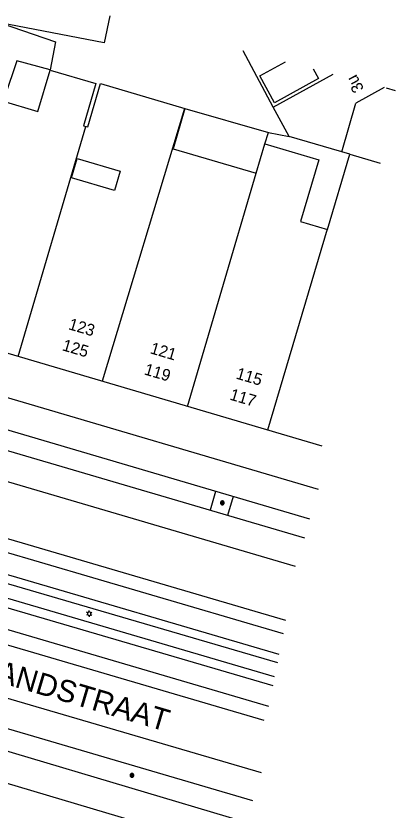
# Model space of a CAD drawing. Extents: x 81065 to 81486, y 452384 to 452681.
# Drawn here: x 81331.8 to 81357.7, y 452503.7 to 452557.9 of the extents above; entities that cross this region are included whole.
import ezdxf

# ---------------------------------------------------------------- set-up
doc = ezdxf.new("R2010")
doc.units = 0
for name, color, linetype in [('B-BH-AL-TOPOGRAFIE_HUISNUMMER-T25', 7, 'Continuous'), ('B-BH-AL-TOPOGRAFIE_STRAATNAAM-S', 7, 'Continuous'), ('B-BH-GR-BOOM-S', 7, 'Continuous'), ('B-BH-IE-MEUBILAIR_WEGMEUBILAIR_LICHTMAST-S', 7, 'Continuous'), ('B-BH-OG-TERREIN_ERF-GV', 7, 'Continuous'), ('B-BH-OG-TOPOGRAFIE_BEBOUWING-GV', 7, 'Continuous'), ('B-BH-OG-TOPOGRAFIE_BEBOUWING_PANDSCHEIDING-GV', 7, 'Continuous'), ('B-BH-VH-KANTOPSLUITING-GV', 7, 'Continuous'), ('B-SB-OG-WEG_SPOOR_TRAM-G', 7, 'Continuous')]:
    doc.layers.add(name, color=color, linetype=linetype)

msp = doc.modelspace()

# ---------------------------------------------------------------- linework, layer by layer
at = {"layer": 'B-BH-GR-BOOM-S'}
for points in [[(81345.8, 452524.656), (81345.8, 452524.643), (81345.802, 452524.63), (81345.806, 452524.616), (81345.811, 452524.604), (81345.817, 452524.592), (81345.824, 452524.581), (81345.833, 452524.57), (81345.842, 452524.561), (81345.853, 452524.552), (81345.864, 452524.545), (81345.876, 452524.539), (81345.889, 452524.534), (81345.902, 452524.53), (81345.915, 452524.528), (81345.928, 452524.527), (81345.942, 452524.528), (81345.955, 452524.53), (81345.968, 452524.534), (81345.981, 452524.539), (81345.993, 452524.545), (81346.004, 452524.552), (81346.015, 452524.561), (81346.024, 452524.57), (81346.033, 452524.581), (81346.04, 452524.592), (81346.046, 452524.604), (81346.051, 452524.616), (81346.054, 452524.63), (81346.056, 452524.643), (81346.057, 452524.656), (81346.056, 452524.67), (81346.054, 452524.683), (81346.051, 452524.696), (81346.046, 452524.709), (81346.04, 452524.721), (81346.033, 452524.732), (81346.024, 452524.743), (81346.015, 452524.752), (81346.004, 452524.761), (81345.993, 452524.768), (81345.981, 452524.774), (81345.968, 452524.779), (81345.955, 452524.782), (81345.942, 452524.784), (81345.928, 452524.785), (81345.915, 452524.784), (81345.902, 452524.782), (81345.889, 452524.779), (81345.876, 452524.774), (81345.864, 452524.768), (81345.853, 452524.761), (81345.842, 452524.752), (81345.833, 452524.743), (81345.824, 452524.732), (81345.817, 452524.721), (81345.811, 452524.709), (81345.806, 452524.696), (81345.802, 452524.683), (81345.8, 452524.67), (81345.8, 452524.656)], [(81345.824, 452524.656), (81345.825, 452524.645), (81345.826, 452524.635), (81345.829, 452524.624), (81345.833, 452524.614), (81345.838, 452524.604), (81345.844, 452524.595), (81345.851, 452524.586), (81345.858, 452524.579), (81345.867, 452524.572), (81345.876, 452524.566), (81345.886, 452524.561), (81345.896, 452524.557), (81345.907, 452524.554), (81345.917, 452524.552), (81345.928, 452524.552), (81345.939, 452524.552), (81345.95, 452524.554), (81345.961, 452524.557), (81345.971, 452524.561), (81345.981, 452524.566), (81345.99, 452524.572), (81345.998, 452524.579), (81346.006, 452524.586), (81346.013, 452524.595), (81346.019, 452524.604), (81346.024, 452524.614), (81346.028, 452524.624), (81346.03, 452524.635), (81346.032, 452524.645), (81346.033, 452524.656), (81346.032, 452524.667), (81346.03, 452524.678), (81346.028, 452524.689), (81346.024, 452524.699), (81346.019, 452524.709), (81346.013, 452524.718), (81346.006, 452524.726), (81345.998, 452524.734), (81345.99, 452524.741), (81345.981, 452524.747), (81345.971, 452524.752), (81345.961, 452524.756), (81345.95, 452524.758), (81345.939, 452524.76), (81345.928, 452524.761), (81345.917, 452524.76), (81345.907, 452524.758), (81345.896, 452524.756), (81345.886, 452524.752), (81345.876, 452524.747), (81345.867, 452524.741), (81345.858, 452524.734), (81345.851, 452524.726), (81345.844, 452524.718), (81345.838, 452524.709), (81345.833, 452524.699), (81345.829, 452524.689), (81345.826, 452524.678), (81345.825, 452524.667), (81345.824, 452524.656)], [(81345.847, 452524.656), (81345.847, 452524.648), (81345.849, 452524.639), (81345.851, 452524.631), (81345.854, 452524.623), (81345.858, 452524.615), (81345.862, 452524.608), (81345.868, 452524.602), (81345.874, 452524.596), (81345.88, 452524.59), (81345.888, 452524.586), (81345.895, 452524.582), (81345.903, 452524.579), (81345.911, 452524.577), (81345.92, 452524.575), (81345.928, 452524.575), (81345.937, 452524.575), (81345.945, 452524.577), (81345.954, 452524.579), (81345.962, 452524.582), (81345.969, 452524.586), (81345.976, 452524.59), (81345.983, 452524.596), (81345.989, 452524.602), (81345.994, 452524.608), (81345.999, 452524.615), (81346.003, 452524.623), (81346.006, 452524.631), (81346.008, 452524.639), (81346.009, 452524.648), (81346.01, 452524.656), (81346.009, 452524.665), (81346.008, 452524.673), (81346.006, 452524.682), (81346.003, 452524.689), (81345.999, 452524.697), (81345.994, 452524.704), (81345.989, 452524.711), (81345.983, 452524.717), (81345.976, 452524.722), (81345.969, 452524.727), (81345.962, 452524.731), (81345.954, 452524.734), (81345.945, 452524.736), (81345.937, 452524.737), (81345.928, 452524.738), (81345.92, 452524.737), (81345.911, 452524.736), (81345.903, 452524.734), (81345.895, 452524.731), (81345.888, 452524.727), (81345.88, 452524.722), (81345.874, 452524.717), (81345.868, 452524.711), (81345.862, 452524.704), (81345.858, 452524.697), (81345.854, 452524.689), (81345.851, 452524.682), (81345.849, 452524.673), (81345.847, 452524.665), (81345.847, 452524.656)], [(81345.87, 452524.656), (81345.87, 452524.65), (81345.871, 452524.644), (81345.873, 452524.638), (81345.875, 452524.632), (81345.878, 452524.627), (81345.881, 452524.622), (81345.885, 452524.617), (81345.889, 452524.613), (81345.894, 452524.609), (81345.899, 452524.605), (81345.905, 452524.603), (81345.91, 452524.6), (81345.916, 452524.599), (81345.922, 452524.598), (81345.928, 452524.598), (81345.935, 452524.598), (81345.941, 452524.599), (81345.947, 452524.6), (81345.952, 452524.603), (81345.958, 452524.605), (81345.963, 452524.609), (81345.968, 452524.613), (81345.972, 452524.617), (81345.976, 452524.622), (81345.979, 452524.627), (81345.982, 452524.632), (81345.984, 452524.638), (81345.986, 452524.644), (81345.987, 452524.65), (81345.987, 452524.656), (81345.987, 452524.662), (81345.986, 452524.668), (81345.984, 452524.674), (81345.982, 452524.68), (81345.979, 452524.686), (81345.976, 452524.691), (81345.972, 452524.696), (81345.968, 452524.7), (81345.963, 452524.704), (81345.958, 452524.707), (81345.952, 452524.71), (81345.947, 452524.712), (81345.941, 452524.714), (81345.935, 452524.715), (81345.928, 452524.715), (81345.922, 452524.715), (81345.916, 452524.714), (81345.91, 452524.712), (81345.905, 452524.71), (81345.899, 452524.707), (81345.894, 452524.704), (81345.889, 452524.7), (81345.885, 452524.696), (81345.881, 452524.691), (81345.878, 452524.686), (81345.875, 452524.68), (81345.873, 452524.674), (81345.871, 452524.668), (81345.87, 452524.662), (81345.87, 452524.656)], [(81345.893, 452524.656), (81345.893, 452524.653), (81345.893, 452524.649), (81345.894, 452524.645), (81345.896, 452524.642), (81345.897, 452524.638), (81345.899, 452524.635), (81345.902, 452524.632), (81345.904, 452524.63), (81345.907, 452524.627), (81345.91, 452524.625), (81345.914, 452524.624), (81345.917, 452524.622), (81345.921, 452524.621), (81345.925, 452524.621), (81345.928, 452524.62), (81345.932, 452524.621), (81345.936, 452524.621), (81345.939, 452524.622), (81345.943, 452524.624), (81345.946, 452524.625), (81345.949, 452524.627), (81345.952, 452524.63), (81345.955, 452524.632), (81345.957, 452524.635), (81345.959, 452524.638), (81345.961, 452524.642), (81345.962, 452524.645), (81345.963, 452524.649), (81345.964, 452524.653), (81345.964, 452524.656), (81345.964, 452524.66), (81345.963, 452524.664), (81345.962, 452524.667), (81345.961, 452524.671), (81345.959, 452524.674), (81345.957, 452524.677), (81345.955, 452524.68), (81345.952, 452524.683), (81345.949, 452524.685), (81345.946, 452524.687), (81345.943, 452524.689), (81345.939, 452524.69), (81345.936, 452524.691), (81345.932, 452524.692), (81345.928, 452524.692), (81345.925, 452524.692), (81345.921, 452524.691), (81345.917, 452524.69), (81345.914, 452524.689), (81345.91, 452524.687), (81345.907, 452524.685), (81345.904, 452524.683), (81345.902, 452524.68), (81345.899, 452524.677), (81345.897, 452524.674), (81345.896, 452524.671), (81345.894, 452524.667), (81345.893, 452524.664), (81345.893, 452524.66), (81345.893, 452524.656)], [(81345.915, 452524.656), (81345.915, 452524.655), (81345.916, 452524.654), (81345.916, 452524.652), (81345.917, 452524.651), (81345.917, 452524.65), (81345.918, 452524.649), (81345.919, 452524.648), (81345.92, 452524.647), (81345.921, 452524.646), (81345.922, 452524.645), (81345.923, 452524.645), (81345.924, 452524.644), (81345.926, 452524.644), (81345.927, 452524.643), (81345.928, 452524.643), (81345.93, 452524.643), (81345.931, 452524.644), (81345.932, 452524.644), (81345.934, 452524.645), (81345.935, 452524.645), (81345.936, 452524.646), (81345.937, 452524.647), (81345.938, 452524.648), (81345.939, 452524.649), (81345.94, 452524.65), (81345.94, 452524.651), (81345.941, 452524.652), (81345.941, 452524.654), (81345.941, 452524.655), (81345.941, 452524.656), (81345.941, 452524.658), (81345.941, 452524.659), (81345.941, 452524.66), (81345.94, 452524.662), (81345.94, 452524.663), (81345.939, 452524.664), (81345.938, 452524.665), (81345.937, 452524.666), (81345.936, 452524.667), (81345.935, 452524.667), (81345.934, 452524.668), (81345.932, 452524.669), (81345.931, 452524.669), (81345.93, 452524.669), (81345.928, 452524.669), (81345.927, 452524.669), (81345.926, 452524.669), (81345.924, 452524.669), (81345.923, 452524.668), (81345.922, 452524.667), (81345.921, 452524.667), (81345.92, 452524.666), (81345.919, 452524.665), (81345.918, 452524.664), (81345.917, 452524.663), (81345.917, 452524.662), (81345.916, 452524.66), (81345.916, 452524.659), (81345.915, 452524.658), (81345.915, 452524.656)], [(81339.627, 452506.026), (81339.628, 452506.012), (81339.63, 452505.999), (81339.633, 452505.986), (81339.638, 452505.974), (81339.644, 452505.962), (81339.652, 452505.95), (81339.66, 452505.94), (81339.67, 452505.93), (81339.68, 452505.922), (81339.692, 452505.914), (81339.704, 452505.908), (81339.716, 452505.903), (81339.729, 452505.9), (81339.742, 452505.898), (81339.756, 452505.897), (81339.769, 452505.898), (81339.783, 452505.9), (81339.796, 452505.903), (81339.808, 452505.908), (81339.82, 452505.914), (81339.832, 452505.922), (81339.842, 452505.93), (81339.852, 452505.94), (81339.86, 452505.95), (81339.868, 452505.962), (81339.874, 452505.974), (81339.878, 452505.986), (81339.882, 452505.999), (81339.884, 452506.012), (81339.885, 452506.026), (81339.884, 452506.039), (81339.882, 452506.053), (81339.878, 452506.066), (81339.874, 452506.078), (81339.868, 452506.09), (81339.86, 452506.102), (81339.852, 452506.112), (81339.842, 452506.122), (81339.832, 452506.13), (81339.82, 452506.138), (81339.808, 452506.144), (81339.796, 452506.148), (81339.783, 452506.152), (81339.769, 452506.154), (81339.756, 452506.155), (81339.742, 452506.154), (81339.729, 452506.152), (81339.716, 452506.148), (81339.704, 452506.144), (81339.692, 452506.138), (81339.68, 452506.13), (81339.67, 452506.122), (81339.66, 452506.112), (81339.652, 452506.102), (81339.644, 452506.09), (81339.638, 452506.078), (81339.633, 452506.066), (81339.63, 452506.053), (81339.628, 452506.039), (81339.627, 452506.026)], [(81339.652, 452506.026), (81339.652, 452506.015), (81339.654, 452506.004), (81339.657, 452505.994), (81339.661, 452505.983), (81339.665, 452505.974), (81339.671, 452505.965), (81339.678, 452505.956), (81339.686, 452505.948), (81339.695, 452505.941), (81339.704, 452505.935), (81339.713, 452505.931), (81339.724, 452505.927), (81339.734, 452505.924), (81339.745, 452505.922), (81339.756, 452505.922), (81339.767, 452505.922), (81339.778, 452505.924), (81339.788, 452505.927), (81339.798, 452505.931), (81339.808, 452505.935), (81339.817, 452505.941), (81339.826, 452505.948), (81339.834, 452505.956), (81339.84, 452505.965), (81339.846, 452505.974), (81339.851, 452505.983), (81339.855, 452505.994), (81339.858, 452506.004), (81339.86, 452506.015), (81339.86, 452506.026), (81339.86, 452506.037), (81339.858, 452506.048), (81339.855, 452506.058), (81339.851, 452506.068), (81339.846, 452506.078), (81339.84, 452506.087), (81339.834, 452506.096), (81339.826, 452506.104), (81339.817, 452506.11), (81339.808, 452506.116), (81339.798, 452506.121), (81339.788, 452506.125), (81339.778, 452506.128), (81339.767, 452506.13), (81339.756, 452506.13), (81339.745, 452506.13), (81339.734, 452506.128), (81339.724, 452506.125), (81339.713, 452506.121), (81339.704, 452506.116), (81339.695, 452506.11), (81339.686, 452506.104), (81339.678, 452506.096), (81339.671, 452506.087), (81339.665, 452506.078), (81339.661, 452506.068), (81339.657, 452506.058), (81339.654, 452506.048), (81339.652, 452506.037), (81339.652, 452506.026)], [(81339.674, 452506.026), (81339.675, 452506.017), (81339.676, 452506.009), (81339.678, 452506.001), (81339.681, 452505.993), (81339.685, 452505.985), (81339.69, 452505.978), (81339.695, 452505.971), (81339.701, 452505.965), (81339.708, 452505.96), (81339.715, 452505.955), (81339.723, 452505.951), (81339.731, 452505.948), (81339.739, 452505.946), (81339.747, 452505.945), (81339.756, 452505.944), (81339.764, 452505.945), (81339.773, 452505.946), (81339.781, 452505.948), (81339.789, 452505.951), (81339.797, 452505.955), (81339.804, 452505.96), (81339.811, 452505.965), (81339.817, 452505.971), (81339.822, 452505.978), (81339.827, 452505.985), (81339.83, 452505.993), (81339.834, 452506.001), (81339.836, 452506.009), (81339.837, 452506.017), (81339.838, 452506.026), (81339.837, 452506.034), (81339.836, 452506.043), (81339.834, 452506.051), (81339.83, 452506.059), (81339.827, 452506.067), (81339.822, 452506.074), (81339.817, 452506.081), (81339.811, 452506.087), (81339.804, 452506.092), (81339.797, 452506.097), (81339.789, 452506.1), (81339.781, 452506.104), (81339.773, 452506.106), (81339.764, 452506.107), (81339.756, 452506.108), (81339.747, 452506.107), (81339.739, 452506.106), (81339.731, 452506.104), (81339.723, 452506.1), (81339.715, 452506.097), (81339.708, 452506.092), (81339.701, 452506.087), (81339.695, 452506.081), (81339.69, 452506.074), (81339.685, 452506.067), (81339.681, 452506.059), (81339.678, 452506.051), (81339.676, 452506.043), (81339.675, 452506.034), (81339.674, 452506.026)], [(81339.697, 452506.026), (81339.698, 452506.02), (81339.699, 452506.014), (81339.7, 452506.008), (81339.702, 452506.002), (81339.705, 452505.997), (81339.709, 452505.991), (81339.712, 452505.987), (81339.717, 452505.982), (81339.721, 452505.979), (81339.727, 452505.975), (81339.732, 452505.972), (81339.738, 452505.97), (81339.744, 452505.969), (81339.75, 452505.968), (81339.756, 452505.967), (81339.762, 452505.968), (81339.768, 452505.969), (81339.774, 452505.97), (81339.78, 452505.972), (81339.785, 452505.975), (81339.79, 452505.979), (81339.795, 452505.982), (81339.8, 452505.987), (81339.803, 452505.991), (81339.807, 452505.997), (81339.81, 452506.002), (81339.812, 452506.008), (81339.813, 452506.014), (81339.814, 452506.02), (81339.815, 452506.026), (81339.814, 452506.032), (81339.813, 452506.038), (81339.812, 452506.044), (81339.81, 452506.05), (81339.807, 452506.055), (81339.803, 452506.06), (81339.8, 452506.065), (81339.795, 452506.07), (81339.79, 452506.073), (81339.785, 452506.077), (81339.78, 452506.08), (81339.774, 452506.082), (81339.768, 452506.083), (81339.762, 452506.084), (81339.756, 452506.085), (81339.75, 452506.084), (81339.744, 452506.083), (81339.738, 452506.082), (81339.732, 452506.08), (81339.727, 452506.077), (81339.721, 452506.073), (81339.717, 452506.07), (81339.712, 452506.065), (81339.709, 452506.06), (81339.705, 452506.055), (81339.702, 452506.05), (81339.7, 452506.044), (81339.699, 452506.038), (81339.698, 452506.032), (81339.697, 452506.026)], [(81339.72, 452506.026), (81339.72, 452506.022), (81339.721, 452506.019), (81339.722, 452506.015), (81339.723, 452506.011), (81339.725, 452506.008), (81339.727, 452506.005), (81339.729, 452506.002), (81339.732, 452505.999), (81339.735, 452505.997), (81339.738, 452505.995), (81339.741, 452505.993), (81339.745, 452505.992), (81339.749, 452505.991), (81339.752, 452505.99), (81339.756, 452505.99), (81339.76, 452505.99), (81339.763, 452505.991), (81339.767, 452505.992), (81339.771, 452505.993), (81339.774, 452505.995), (81339.777, 452505.997), (81339.78, 452505.999), (81339.782, 452506.002), (81339.785, 452506.005), (81339.787, 452506.008), (81339.789, 452506.011), (81339.79, 452506.015), (81339.791, 452506.019), (81339.792, 452506.022), (81339.792, 452506.026), (81339.792, 452506.03), (81339.791, 452506.033), (81339.79, 452506.037), (81339.789, 452506.041), (81339.787, 452506.044), (81339.785, 452506.047), (81339.782, 452506.05), (81339.78, 452506.052), (81339.777, 452506.055), (81339.774, 452506.057), (81339.771, 452506.059), (81339.767, 452506.06), (81339.763, 452506.061), (81339.76, 452506.062), (81339.756, 452506.062), (81339.752, 452506.062), (81339.749, 452506.061), (81339.745, 452506.06), (81339.741, 452506.059), (81339.738, 452506.057), (81339.735, 452506.055), (81339.732, 452506.052), (81339.729, 452506.05), (81339.727, 452506.047), (81339.725, 452506.044), (81339.723, 452506.041), (81339.722, 452506.037), (81339.721, 452506.033), (81339.72, 452506.03), (81339.72, 452506.026)], [(81339.743, 452506.026), (81339.743, 452506.025), (81339.743, 452506.023), (81339.744, 452506.022), (81339.744, 452506.021), (81339.745, 452506.02), (81339.746, 452506.018), (81339.746, 452506.017), (81339.747, 452506.016), (81339.748, 452506.016), (81339.75, 452506.015), (81339.751, 452506.014), (81339.752, 452506.014), (81339.753, 452506.013), (81339.755, 452506.013), (81339.756, 452506.013), (81339.757, 452506.013), (81339.759, 452506.013), (81339.76, 452506.014), (81339.761, 452506.014), (81339.762, 452506.015), (81339.764, 452506.016), (81339.765, 452506.016), (81339.766, 452506.017), (81339.766, 452506.018), (81339.767, 452506.02), (81339.768, 452506.021), (81339.768, 452506.022), (81339.769, 452506.023), (81339.769, 452506.025), (81339.769, 452506.026), (81339.769, 452506.027), (81339.769, 452506.029), (81339.768, 452506.03), (81339.768, 452506.031), (81339.767, 452506.032), (81339.766, 452506.034), (81339.766, 452506.035), (81339.765, 452506.036), (81339.764, 452506.036), (81339.762, 452506.037), (81339.761, 452506.038), (81339.76, 452506.038), (81339.759, 452506.039), (81339.757, 452506.039), (81339.756, 452506.039), (81339.755, 452506.039), (81339.753, 452506.039), (81339.752, 452506.038), (81339.751, 452506.038), (81339.75, 452506.037), (81339.748, 452506.036), (81339.747, 452506.036), (81339.746, 452506.035), (81339.746, 452506.034), (81339.745, 452506.032), (81339.744, 452506.031), (81339.744, 452506.03), (81339.743, 452506.029), (81339.743, 452506.027), (81339.743, 452506.026)]]:
    msp.add_lwpolyline(points, dxfattribs=at)
at = {"layer": 'B-BH-IE-MEUBILAIR_WEGMEUBILAIR_LICHTMAST-S'}
for p, q in [((81336.835, 452517.199), (81336.835, 452517.291)), ((81336.729, 452517.138), (81336.65, 452517.184)), ((81336.729, 452517.016), (81336.65, 452516.97)), ((81336.835, 452516.955), (81336.835, 452516.863)), ((81336.94, 452517.138), (81337.02, 452517.184)), ((81336.94, 452517.016), (81337.02, 452516.97))]:
    msp.add_line(p, q, dxfattribs=at)
msp.add_lwpolyline([(81336.713, 452517.077), (81336.714, 452517.064), (81336.715, 452517.051), (81336.719, 452517.039), (81336.723, 452517.027), (81336.729, 452517.016), (81336.736, 452517.005), (81336.744, 452516.995), (81336.753, 452516.986), (81336.763, 452516.978), (81336.774, 452516.971), (81336.785, 452516.965), (81336.797, 452516.961), (81336.81, 452516.957), (81336.822, 452516.956), (81336.835, 452516.955), (81336.848, 452516.956), (81336.86, 452516.957), (81336.873, 452516.961), (81336.885, 452516.965), (81336.896, 452516.971), (81336.907, 452516.978), (81336.917, 452516.986), (81336.926, 452516.995), (81336.934, 452517.005), (81336.941, 452517.016), (81336.946, 452517.027), (81336.951, 452517.039), (81336.954, 452517.051), (81336.956, 452517.064), (81336.957, 452517.077), (81336.956, 452517.09), (81336.954, 452517.102), (81336.951, 452517.115), (81336.946, 452517.127), (81336.941, 452517.138), (81336.934, 452517.149), (81336.926, 452517.159), (81336.917, 452517.168), (81336.907, 452517.176), (81336.896, 452517.183), (81336.885, 452517.188), (81336.873, 452517.193), (81336.86, 452517.196), (81336.848, 452517.198), (81336.835, 452517.199), (81336.822, 452517.198), (81336.809, 452517.196), (81336.797, 452517.193), (81336.785, 452517.188), (81336.774, 452517.183), (81336.763, 452517.176), (81336.753, 452517.168), (81336.744, 452517.159), (81336.736, 452517.149), (81336.729, 452517.138), (81336.723, 452517.127), (81336.719, 452517.115), (81336.715, 452517.102), (81336.714, 452517.09), (81336.713, 452517.077)], dxfattribs=at)
at = {"layer": 'B-BH-OG-TERREIN_ERF-GV'}
for p, q in [((81349.404, 452551.704), (81347.364, 452555.567)), ((81343.378, 452551.616), (81349.084, 452549.985)), ((81348.824, 452549.198), (81349.084, 452549.985)), ((81349.084, 452549.985), (81350.501, 452549.691))]:
    msp.add_line(p, q, dxfattribs=at)
at = {"layer": 'B-BH-OG-TOPOGRAFIE_BEBOUWING-GV'}
for points in [[(81338.238, 452557.947), (81337.858, 452556.099), (81330.729, 452557.473), (81334.535, 452556.176), (81334.163, 452554.262), (81331.895, 452554.876), (81331.062, 452552.431)], [(81352.137, 452554.323), (81352.496, 452553.664), (81349.504, 452552.008), (81348.497, 452553.854), (81350.255, 452554.813)], [(81330.891, 452552.13), (81333.331, 452551.411), (81334.17, 452554.245), (81337.297, 452553.332), (81336.443, 452550.436), (81336.73, 452550.351), (81337.604, 452553.318), (81343.378, 452551.616), (81342.565, 452548.859), (81348.232, 452547.189), (81348.824, 452549.198), (81352.513, 452548.11), (81351.272, 452543.9), (81353.124, 452543.354), (81354.638, 452548.487), (81350.501, 452549.691), (81349.404, 452551.704), (81353.495, 452553.969)], [(81357.129, 452553.021), (81357.736, 452552.841)], [(81336.016, 452548.186), (81338.946, 452547.321), (81338.56, 452546.011), (81335.629, 452546.876), (81336.016, 452548.186)], [(81352.743, 452528.537), (81324.103, 452536.977), (81314.746, 452539.742), (81314.625, 452539.322), (81308.624, 452541.116), (81308.653, 452541.212), (81305.913, 452542.046), (81301.274, 452539.437), (81301.31, 452539.356), (81296.807, 452536.892), (81297.009, 452536.514), (81289.586, 452532.489), (81286.276, 452538.555)]]:
    msp.add_lwpolyline(points, dxfattribs=at)
at = {"layer": 'B-BH-OG-TOPOGRAFIE_BEBOUWING_PANDSCHEIDING-GV'}
for p, q in [((81356.996, 452553.056), (81355.059, 452551.98)), ((81354.089, 452548.647), (81355.059, 452551.98)), ((81343.343, 452551.626), (81337.721, 452532.964)), ((81331.979, 452534.656), (81336.605, 452550.388)), ((81354.638, 452548.487), (81356.717, 452547.882)), ((81343.56, 452531.242), (81348.232, 452547.189)), ((81353.094, 452543.363), (81349.012, 452529.636))]:
    msp.add_line(p, q, dxfattribs=at)
at = {"layer": 'B-BH-VH-KANTOPSLUITING-GV'}
for p, q in [((81352.503, 452525.578), (81323.149, 452534.212)), ((81351.904, 452523.541), (81322.55, 452532.174)), ((81351.559, 452522.249), (81322.173, 452530.891)), ((81350.921, 452520.313), (81321.567, 452528.947)), ((81350.267, 452516.603), (81320.385, 452525.392)), ((81345.466, 452525.434), (81345.089, 452524.152)), ((81346.668, 452525.081), (81346.291, 452523.798)), ((81348.8, 452509.768), (81323.129, 452517.302)), ((81348.596, 452506.196), (81324.541, 452513.255)), ((81348.008, 452504.29), (81323.953, 452511.349))]:
    msp.add_line(p, q, dxfattribs=at)
for points in [[(81349.504, 452512.77), (81323.954, 452520.258), (81322.698, 452520.618), (81320.763, 452521.165), (81319.162, 452521.68), (81315.937, 452522.574), (81314.308, 452522.856), (81312.201, 452523.234), (81308.417, 452523.508), (81304.625, 452523.382), (81301.432, 452522.893), (81297.755, 452521.956), (81295.934, 452521.282), (81294.197, 452520.638), (81290.798, 452518.952), (81290.58, 452518.897), (81290.188, 452519.081), (81290.092, 452519.503), (81290.366, 452519.838), (81293.495, 452521.416), (81297.06, 452522.785), (81300.748, 452523.773), (81304.519, 452524.371)], [(81304.519, 452524.371), (81308.028, 452524.506), (81311.881, 452524.274), (81314.565, 452523.83), (81315.673, 452523.653), (81319.345, 452522.668), (81321.128, 452522.091), (81324.056, 452521.245), (81349.704, 452513.741)], [(81347.493, 452502.83), (81323.617, 452509.943)], [(81346.914, 452500.791), (81323.025, 452507.908)]]:
    msp.add_lwpolyline(points, dxfattribs=at)
at = {"layer": 'B-SB-OG-WEG_SPOOR_TRAM-G'}
for p, q in [((81350.107, 452515.706), (81320.421, 452524.412)), ((81349.817, 452514.294), (81320.017, 452523.034)), ((81320.98, 452520.496), (81349.38, 452512.166)), ((81320.576, 452519.12), (81349.091, 452510.757))]:
    msp.add_line(p, q, dxfattribs=at)

# ---------------------------------------------------------------- texts
at = {"layer": 'B-BH-AL-TOPOGRAFIE_HUISNUMMER-T25'}
for s, rotation, p in [('3u', 118.6618, (81355.631, 452552.961)), ('123', 343.5819, (81335.363, 452536.535)), ('125', 343.5819, (81334.939, 452535.096)), ('121', 343.5819, (81340.944, 452534.89)), ('119', 343.5819, (81340.538, 452533.446)), ('115', 343.5819, (81346.809, 452533.162)), ('117', 343.5819, (81346.382, 452531.724))]:
    msp.add_text(s, height=0.8, rotation=rotation, dxfattribs=at).set_placement(p)
at = {"layer": 'B-BH-AL-TOPOGRAFIE_STRAATNAAM-S'}
msp.add_text('HILDEBRANDSTRAAT', height=1.5, rotation=343.4847, dxfattribs=at).set_placement((81322.062, 452514.938))

doc.saveas('drawing.dxf')
